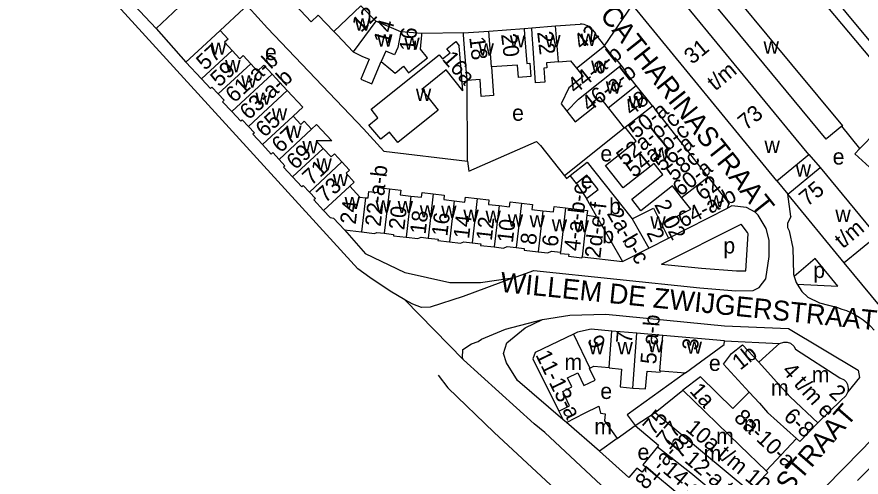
# Model space of a CAD drawing. Extents: x 160673 to 161924, y 382258 to 384145.
# Drawn here: x 160762.5 to 160974.8, y 382888.8 to 383004.5 of the extents above; entities that cross this region are included whole.
import ezdxf

# ---------------------------------------------------------------- set-up
doc = ezdxf.new("R2010")
doc.units = 0
for name, color, linetype in [('BLT_Basislijn', 7, 'Continuous'), ('BLT_Bebouwing', 7, 'Continuous'), ('BLT_Centroide', 7, 'Continuous'), ('BLT_Huisnummer', 7, 'Continuous'), ('BLT_Huisnummer_ tussenligend', 7, 'Continuous'), ('BLT_Huisnummer_reeks', 7, 'Continuous'), ('BLT_Onderdoorgang_en_onderverdeling', 7, 'Continuous'), ('BLT_Onderverdeling_panden', 7, 'Continuous'), ('BLT_Straatnaam', 7, 'Continuous'), ('BLT_Vlakafsluiter', 7, 'Continuous')]:
    doc.layers.add(name, color=color, linetype=linetype)

msp = doc.modelspace()

# ---------------------------------------------------------------- linework, layer by layer
at = {"layer": 'BLT_Basislijn'}
for p, q in [((160797.51, 383001.64), (160805.02, 382993.11)), ((160874.79, 383000.47), (160864.31, 383000.33)), ((160890.02, 383001.64), (160891.98, 383001.79)), ((160875.8, 382968.26), (160875.69, 382988.54)), ((160974.46, 382971.4), (160969.96, 382977.04)), ((160915.17, 382976.53), (160900.18, 382964.55)), ((160903.21, 382962.64), (160905.71, 382958.85)), ((160957.08, 382954.31), (160956.31, 382959.97)), ((160844.89, 382950.95), (160850.14, 382944.96)), ((160958.71, 382937.3), (160968.88, 382936.83)), ((160940.45, 382923.03), (160954.21, 382922.38)), ((160974.01, 382915.66), (160974.4, 382913.88)), ((160930.62, 382915.04), (160915.98, 382904.45)), ((160898.77, 382905.41), (160899.8, 382903.34)), ((160900.73, 382902.52), (160899.79, 382903.27)), ((160913.4, 382898.5), (160917.97, 382901.75)), ((160916.4, 382888.68), (160909.03, 382895.35))]:
    msp.add_line(p, q, dxfattribs=at)
for points in [[(160860.05, 382933.37), (160856.38, 382935.54), (160851.3, 382939), (160848.28, 382941.16), (160762.53, 383035.18)], [(160951.81, 383024.3), (160982.58, 382987.62), (160979.94, 382985.6), (160984.16, 382980.62)], [(160963.06, 383015.22), (160978.82, 382996.13), (160992.96, 383008.58), (160973.33, 383023.89)], [(160813.63, 383001.08), (160819.55, 383006.65), (160820.69, 383007.01), (160825.54, 383001.66), (160849.63, 382976.37), (160854.76, 382970.79), (160875.8, 382968.26)], [(160875.8, 382968.26), (160876.19, 382965.75), (160893.19, 382973.16), (160894.15, 382972.21), (160900.18, 382964.55)], [(160900.18, 382964.55), (160900.73, 382963.86), (160901.65, 382964.6)], [(160887.14, 382938.82), (160892.45, 382940.72), (160934.23, 382936.35), (160943.29, 382935.67), (160947.63, 382935.71), (160949.16, 382936.51), (160950.81, 382938.68), (160951.69, 382944.29), (160951.69, 382948.35), (160950.91, 382951.27), (160948.9, 382954.68), (160948.17, 382955.38), (160945.97, 382956.59), (160942.3, 382956.99), (160941.17, 382956.43)], [(160957.08, 382954.31), (160956.3, 382952.54), (160956.27, 382951.57), (160956.66, 382950.72), (160957.58, 382946.36), (160957.74, 382939.86), (160957.94, 382939.27)], [(160924.61, 382942.38), (160944.6, 382952.39)], [(160945.82, 382940.69), (160946.35, 382949.93), (160946.2, 382950.27), (160944.6, 382952.39)], [(160887.14, 382938.82), (160879.05, 382937.63), (160871.34, 382937.67), (160860.15, 382940.12), (160850.14, 382944.96)], [(160968.88, 382936.83), (160963.2, 382943.73), (160957.94, 382939.27)], [(160924.61, 382942.38), (160934.67, 382941.33), (160943.45, 382940.67), (160945.82, 382940.69)], [(160887.14, 382938.82), (160874.73, 382934.18), (160866.44, 382931.51), (160864.29, 382931.44), (160862.06, 382932.26), (160860.05, 382933.37)], [(160957.94, 382939.27), (160958.43, 382937.77), (160958.71, 382937.3)], [(160958.71, 382937.3), (160959.85, 382935.43), (160961.39, 382934.02), (160964.3, 382932.61), (160968.85, 382931.43), (160969.96, 382931.06)], [(160969.96, 382931.06), (160971.09, 382930.66), (160972.19, 382930.19), (160973.25, 382929.64), (160974.28, 382929.02), (160975.27, 382928.34), (160976.2, 382927.59), (160977.09, 382926.78), (160978.08, 382925.73)], [(160878.49, 382922.86), (160879.36, 382923.44), (160885.38, 382925.99), (160894.65, 382928.42)], [(160899.79, 382903.27), (160888.35, 382913.06), (160885.58, 382917.54), (160884.9, 382919.9), (160885.69, 382922.52), (160890.29, 382926.32), (160894.65, 382928.42)], [(160894.65, 382928.42), (160901.58, 382929.48), (160910.63, 382929.79), (160940.41, 382926.83), (160956.55, 382926.15), (160974.01, 382915.66)], [(160874.8, 382918.27), (160874.53, 382918.82), (160874.68, 382920.86), (160876.8, 382922.32), (160878.49, 382922.86)], [(160929.92, 382867.53), (160895.25, 382900), (160892.57, 382902.21), (160874.8, 382918.27)], [(160868.45, 382914.46), (160870.91, 382911.22), (160882.54, 382900), (160909.7, 382874.79), (160911.87, 382872.51), (160924.34, 382861.03)], [(160974.4, 382913.88), (160971.41, 382910.23)], [(160986.23, 382906.1), (160979.59, 382900.39), (160974.77, 382895.48), (160965.77, 382886.24), (160962.43, 382882.73), (160958.51, 382877.83), (160957.53, 382876.57)]]:
    msp.add_lwpolyline(points, dxfattribs=at)
at = {"layer": 'BLT_Bebouwing'}
for p, q in [((160790.69, 383008.95), (160797.51, 383001.64)), ((160803.22, 383006.98), (160797.51, 383001.64)), ((160852.76, 383003.41), (160849.04, 383007.31)), ((160838.29, 383004.96), (160842.23, 383000.83)), ((160859.08, 383000.74), (160852.76, 383003.41)), ((160897.97, 383002.25), (160904.18, 383002.73)), ((160864.31, 383000.33), (160859.08, 383000.74)), ((160874.79, 383000.47), (160881.14, 383000.96)), ((160881.14, 383000.96), (160890.02, 383001.64)), ((160891.98, 383001.79), (160897.97, 383002.25)), ((160874.68, 382985.92), (160873.68, 382997.28)), ((160826.7, 382990.14), (160830.51, 382986.03)), ((160922.29, 382982.15), (160918.2, 382987.26)), ((160922.29, 382982.15), (160922.87, 382981.37)), ((160927.24, 382975.83), (160922.87, 382981.37)), ((160915.17, 382976.53), (160915.48, 382976.79)), ((160931.7, 382970.18), (160927.24, 382975.83)), ((160936.3, 382964.33), (160931.7, 382970.18)), ((160961.64, 382969.95), (160964.45, 382966.67)), ((160903.21, 382962.64), (160901.65, 382964.6)), ((160953.59, 382963.33), (160956.31, 382959.97)), ((160908.24, 382954.44), (160905.71, 382958.85)), ((160844.89, 382950.95), (160849.17, 382950.45)), ((160914.77, 382943), (160921.44, 382946.39)), ((160902.46, 382924.75), (160892.82, 382920.11)), ((160918.37, 382924.95), (160912.13, 382925.5)), ((160924.88, 382924.39), (160918.37, 382924.95)), ((160940.45, 382923.03), (160924.88, 382924.39)), ((160924.32, 382915.54), (160930.62, 382915.04)), ((160922.98, 382905.02), (160929.95, 382910.64)), ((160915.98, 382904.45), (160917.97, 382901.75)), ((160909.03, 382895.35), (160900.73, 382902.52)), ((160913.4, 382898.5), (160909.03, 382895.35)), ((160950.91, 382890.34), (160958.56, 382898.5)), ((160982.84, 382896.92), (160973.86, 382887.97))]:
    msp.add_line(p, q, dxfattribs=at)
for points in [[(160969.96, 382977.04), (160966.19, 382973.94), (160965.95, 382973.74), (160944.25, 383000), (160933.11, 383013.54), (160933.33, 383013.72), (160937.19, 383016.89)], [(160937.19, 383016.89), (160951.09, 383000), (160970.05, 382977.11), (160969.96, 382977.04)], [(160961.64, 382969.95), (160958.42, 382973.78), (160925.38, 383014.05)], [(160832.49, 383007.52), (160836.53, 383003.28), (160838.29, 383004.96)], [(160953.59, 382963.33), (160917.33, 383007.56)], [(160906.37, 383001.95), (160905.99, 383002.25), (160905.57, 383002.48), (160905.12, 383002.64), (160904.64, 383002.72), (160904.18, 383002.73)], [(160813.63, 383001.08), (160812.5, 383000.03), (160809.11, 382996.9), (160805.02, 382993.11)], [(160813.63, 383001.08), (160814.66, 383000), (160815.62, 382998.95), (160814.74, 382998.13), (160816.65, 382996.06)], [(160842.23, 383000.83), (160843.02, 383000), (160847.11, 382995.72)], [(160856.51, 382991.3), (160857.6, 382990.39), (160859.73, 382992.09), (160861.02, 382990.47), (160861.84, 382991.13), (160865.74, 382994.25), (160864.02, 382996.41), (160864.3, 383000), (160864.31, 383000.33)], [(160875.69, 382988.54), (160875.15, 382995.49), (160874.82, 383000), (160874.79, 383000.47)], [(160890.02, 383001.64), (160890.15, 383000), (160890.72, 382992.8), (160891.5, 382992.86), (160891.75, 382989.54), (160888.6, 382989.3), (160888.36, 382992.42), (160881.83, 382991.92)], [(160898.7, 382993.24), (160895.66, 382993), (160895.76, 382991.68), (160894.97, 382991.62), (160895.24, 382988.08), (160892.94, 382987.9), (160892.29, 382996.64), (160892.04, 383000), (160891.98, 383001.79)], [(160906.37, 383001.95), (160906.88, 383001.34), (160907.23, 383001.3), (160908.01, 383000.31), (160907.89, 383000.21), (160908.06, 383000), (160910.25, 382997.24)], [(160851.58, 382981.28), (160868.69, 382994.96), (160869.5, 382993.95), (160871.43, 382995.49), (160870.62, 382996.5), (160872.87, 382998.3), (160873.68, 382997.28)], [(160914.43, 382992.34), (160912.98, 382994.18), (160912.71, 382994.14), (160910.25, 382997.24)], [(160816.65, 382996.06), (160818.57, 382993.99), (160819.41, 382994.77), (160821.31, 382992.72)], [(160847.11, 382995.72), (160849.26, 382994.66), (160851.1, 382993.88), (160848.97, 382988.84), (160851.77, 382987.66), (160854.14, 382993.27)], [(160805.02, 382993.11), (160808.96, 382988.94)], [(160821.31, 382992.72), (160823.03, 382990.86), (160824.65, 382992.36), (160826.7, 382990.14)], [(160854.14, 382993.27), (160856.51, 382991.3)], [(160881.83, 382991.92), (160882.38, 382984.77), (160879.29, 382984.53), (160878.96, 382988.8), (160875.69, 382988.54)], [(160898.7, 382993.24), (160901.74, 382993.49), (160903.21, 382991.64)], [(160918.2, 382987.26), (160915.71, 382990.42), (160915.79, 382990.62), (160914.43, 382992.34)], [(160874.68, 382985.92), (160870.46, 382991.17), (160864.32, 382986.24), (160868.47, 382981.06), (160858.3, 382972.9), (160856.2, 382975.52), (160854.06, 382973.81), (160851.01, 382977.28), (160853.31, 382979.13), (160851.58, 382981.28)], [(160903.21, 382991.64), (160904.9, 382989.51), (160901.29, 382986.66), (160899.34, 382982.68), (160900.81, 382980.82)], [(160808.96, 382988.94), (160811.22, 382986.49), (160811.58, 382986.83), (160813.13, 382985.15)], [(160830.51, 382986.03), (160834.43, 382981.81), (160831.98, 382979.56)], [(160813.13, 382985.15), (160814.62, 382983.54), (160814.26, 382983.2), (160816.55, 382980.72)], [(160900.81, 382980.82), (160902.92, 382978.14), (160907.77, 382981.96), (160907.06, 382982.87), (160908.98, 382984.39), (160911.14, 382981.65)], [(160911.14, 382981.65), (160913.74, 382978.35), (160915.17, 382976.53)], [(160816.55, 382980.72), (160818.83, 382978.26), (160819.2, 382978.6), (160820.76, 382976.92)], [(160831.98, 382979.56), (160833.9, 382977.49), (160834.78, 382978.3), (160836.61, 382976.32)], [(160836.61, 382976.32), (160837.88, 382977.49), (160841.69, 382973.38), (160837.77, 382973.33), (160839.55, 382971.4)], [(160820.76, 382976.92), (160822.23, 382975.33), (160821.88, 382975.01), (160824.26, 382972.42)], [(160910.49, 382967.15), (160918.25, 382973.27), (160915.48, 382976.79)], [(160978.58, 382975.62), (160974.46, 382971.4)], [(160824.26, 382972.42), (160826.47, 382970.04), (160826.85, 382970.39), (160828.49, 382968.62)], [(160839.55, 382971.4), (160841.5, 382969.3), (160842.36, 382970.1), (160844.25, 382968.05)], [(160974.46, 382971.4), (160973.2, 382970.11), (160976.88, 382966.73), (160978.52, 382965.21), (160977.89, 382964.49)], [(160828.49, 382968.62), (160829.92, 382967.06), (160829.57, 382966.74), (160831.85, 382964.27)], [(160844.25, 382968.05), (160846.15, 382966), (160845.28, 382965.2), (160847.33, 382962.98), (160846.2, 382961.93)], [(160901.65, 382964.6), (160905.88, 382968), (160916.91, 382954.2), (160917.2, 382953.7)], [(160924.96, 382964.86), (160922.74, 382967.67), (160914.94, 382961.52), (160910.49, 382967.15)], [(160964.45, 382966.67), (160978.68, 382949.37)], [(160831.85, 382964.27), (160834.14, 382961.8), (160834.52, 382962.15), (160836.07, 382960.48)], [(160905.71, 382958.85), (160908.68, 382961.1), (160905.81, 382964.71), (160903.21, 382962.64)], [(160929.63, 382959.07), (160927.33, 382962), (160919.39, 382955.75), (160917.1, 382958.67), (160924.96, 382964.86)], [(160941.17, 382956.43), (160941.57, 382957.65), (160936.3, 382964.33)], [(160836.07, 382960.48), (160837.6, 382958.82), (160837.22, 382958.48), (160839.63, 382955.86)], [(160846.2, 382961.93), (160848.71, 382959.22), (160850.15, 382959.06)], [(160850.83, 382958.98), (160851.01, 382960.6), (160853.21, 382960.34), (160853.36, 382961.58), (160856.19, 382961.25)], [(160856.19, 382961.25), (160859.03, 382960.93), (160858.9, 382959.8), (160861.6, 382959.48)], [(160861.6, 382959.48), (160864.29, 382959.17), (160864.43, 382960.36), (160867.2, 382960.04)], [(160867.2, 382960.04), (160869.97, 382959.72), (160869.84, 382958.58), (160872.5, 382958.27)], [(160850.15, 382959.06), (160850.83, 382958.98)], [(160872.5, 382958.27), (160875.15, 382957.97), (160875.29, 382959.17), (160878.24, 382958.83)], [(160878.24, 382958.83), (160881.2, 382958.49), (160881.07, 382957.37), (160883.74, 382957.06)], [(160883.74, 382957.06), (160886.4, 382956.76), (160886.55, 382957.99), (160889.35, 382957.67)], [(160924.57, 382952.4), (160931.94, 382956.15), (160929.63, 382959.07)], [(160970.55, 382942.67), (160956.31, 382959.97)], [(160839.63, 382955.86), (160841.26, 382954.09), (160842.1, 382953.87), (160844.89, 382950.95)], [(160889.35, 382957.67), (160892.16, 382957.35), (160892.02, 382956.1), (160894.74, 382955.79)], [(160894.74, 382955.79), (160897.47, 382955.47), (160897.62, 382956.81), (160900.44, 382956.48)], [(160900.44, 382956.48), (160903.26, 382956.16), (160905.96, 382955.85), (160905.83, 382954.62)], [(160917.2, 382953.7), (160922.54, 382956.41), (160924.57, 382952.4)], [(160926.37, 382948.86), (160941.17, 382956.43)], [(160905.83, 382954.62), (160908.1, 382954.36)], [(160908.1, 382954.36), (160908.24, 382954.44)], [(160849.17, 382950.45), (160852.45, 382950.08), (160853, 382950.32), (160854.9, 382950.1)], [(160854.9, 382950.1), (160857.24, 382949.83), (160857.19, 382949.47), (160860.4, 382949.1)], [(160860.4, 382949.1), (160863.33, 382948.76), (160864.14, 382949.11), (160865.92, 382948.91)], [(160865.92, 382948.91), (160868.4, 382948.62), (160868.36, 382948.26), (160871.3, 382947.92)], [(160871.3, 382947.92), (160874.06, 382947.6), (160874.92, 382947.97), (160876.96, 382947.74)], [(160876.96, 382947.74), (160879.15, 382947.48), (160879.11, 382947.05), (160882.54, 382946.66)], [(160921.44, 382946.39), (160926.37, 382948.86)], [(160882.54, 382946.66), (160884.84, 382946.39), (160885.79, 382946.8), (160888.07, 382946.54)], [(160888.07, 382946.54), (160890.07, 382946.31), (160890.02, 382945.87), (160893.55, 382945.46)], [(160893.55, 382945.46), (160895.99, 382945.18), (160896.96, 382945.6), (160899.16, 382945.35)], [(160899.16, 382945.35), (160899.12, 382945.06), (160901.3, 382944.82), (160901.24, 382944.32), (160904.59, 382943.94), (160904.62, 382944.17)], [(160904.62, 382944.17), (160914.77, 382943)], [(160999.49, 382938.63), (160984.22, 382926.07), (160970.55, 382942.67)], [(160912.13, 382925.5), (160906.93, 382925.99), (160903.49, 382925.26), (160902.46, 382924.75)], [(160930.62, 382915.04), (160940.38, 382922.14), (160940.45, 382923.03)], [(160946.59, 382910.15), (160940.15, 382917.16), (160942.16, 382919.87), (160944.91, 382922.09), (160949.02, 382917.69)], [(160949.02, 382917.69), (160953.51, 382921.76), (160954.21, 382922.38)], [(160954.21, 382922.38), (160955.33, 382922.72), (160956.18, 382922.72), (160957.04, 382922.47), (160957.89, 382921.7), (160958.28, 382920.96), (160969.41, 382913.72), (160970.47, 382913.22), (160970.98, 382912.71), (160971.32, 382912.11), (160971.49, 382911.09), (160971.41, 382910.23)], [(160892.82, 382920.11), (160892.27, 382918.55), (160898.77, 382905.41)], [(160903.53, 382915.01), (160905.1, 382911.79), (160907.91, 382913.15), (160906.46, 382916.14), (160906.61, 382916.22)], [(160906.61, 382916.22), (160907.54, 382916.67), (160911.41, 382916.36)], [(160911.41, 382916.36), (160911.4, 382916.26), (160914.52, 382915.93), (160914.17, 382911.46), (160917.39, 382911.2)], [(160917.39, 382911.2), (160920.6, 382910.95), (160920.96, 382915.42), (160924.29, 382915.16), (160924.32, 382915.54)], [(160900.9, 382910.9), (160902.06, 382911.46), (160900.94, 382913.76), (160903.53, 382915.01)], [(160946.59, 382910.15), (160942.54, 382906.07), (160934.4, 382914.01), (160929.95, 382910.64)], [(160898.77, 382905.41), (160901.49, 382906.73), (160899.74, 382910.34), (160900.9, 382910.9)], [(160971.41, 382910.23), (160970.9, 382909.2), (160969.69, 382908.09), (160963.92, 382902.48)], [(160900.73, 382902.52), (160905.26, 382904.91), (160908.8, 382906.64), (160909.27, 382904.89), (160910.41, 382904.74), (160910.25, 382902.96), (160913.4, 382898.5)], [(160917.97, 382901.75), (160922.98, 382905.02)], [(160917.97, 382901.75), (160923.86, 382896.83), (160923.54, 382896.42)], [(160958.56, 382898.5), (160959.33, 382897.76), (160963.92, 382902.48)], [(160923.54, 382896.42), (160919.93, 382891.86), (160920.61, 382891.34)], [(160920.61, 382891.34), (160919.71, 382890.07), (160918.38, 382891.08), (160916.4, 382888.68)], [(160946.79, 382885.26), (160951.36, 382889.94), (160950.91, 382890.34)]]:
    msp.add_lwpolyline(points, dxfattribs=at)
at = {"layer": 'BLT_Onderdoorgang_en_onderverdeling'}
for p, q in [((160953.59, 382963.33), (160961.64, 382969.95)), ((160956.31, 382959.97), (160964.45, 382966.67))]:
    msp.add_line(p, q, dxfattribs=at)
at = {"layer": 'BLT_Onderverdeling_panden'}
for p, q in [((160842.23, 383000.83), (160849.04, 383007.31)), ((160852.76, 383003.41), (160847.11, 382995.72)), ((160881.83, 382991.92), (160881.14, 383000.96)), ((160898.7, 382993.24), (160897.97, 383002.25)), ((160903.21, 382991.64), (160910.25, 382997.24)), ((160816.65, 382996.06), (160808.96, 382988.94)), ((160821.31, 382992.72), (160813.13, 382985.15)), ((160826.7, 382990.14), (160816.55, 382980.72)), ((160830.51, 382986.03), (160820.76, 382976.92)), ((160911.14, 382981.65), (160918.2, 382987.26)), ((160915.48, 382976.79), (160922.29, 382982.15)), ((160831.98, 382979.56), (160824.26, 382972.42)), ((160836.61, 382976.32), (160828.49, 382968.62)), ((160839.55, 382971.4), (160831.85, 382964.27)), ((160844.25, 382968.05), (160836.07, 382960.48)), ((160929.63, 382959.07), (160936.3, 382964.33)), ((160846.2, 382961.93), (160839.63, 382955.86)), ((160856.19, 382961.25), (160854.9, 382950.1)), ((160867.2, 382960.04), (160865.92, 382948.91)), ((160850.15, 382959.06), (160849.17, 382950.45)), ((160861.6, 382959.48), (160860.4, 382949.1)), ((160872.5, 382958.27), (160871.3, 382947.92)), ((160878.24, 382958.83), (160876.96, 382947.74)), ((160883.74, 382957.06), (160882.54, 382946.66)), ((160889.35, 382957.67), (160888.07, 382946.54)), ((160894.74, 382955.79), (160893.55, 382945.46)), ((160900.44, 382956.48), (160899.16, 382945.35)), ((160905.83, 382954.62), (160904.62, 382944.17)), ((160908.24, 382954.44), (160914.77, 382943)), ((160917.2, 382953.7), (160921.44, 382946.39)), ((160924.57, 382952.4), (160926.37, 382948.86)), ((160978.68, 382949.37), (160970.55, 382942.67)), ((160902.46, 382924.75), (160906.61, 382916.22)), ((160911.41, 382916.36), (160912.13, 382925.5)), ((160917.39, 382911.2), (160918.37, 382924.95)), ((160949.02, 382917.69), (160954.24, 382911.92)), ((160944.27, 382896.76), (160929.95, 382910.64)), ((160946.59, 382910.15), (160949.23, 382907.39)), ((160949.23, 382907.39), (160951.25, 382905.07)), ((160922.98, 382905.02), (160946.79, 382885.26)), ((160951.25, 382905.07), (160958.56, 382898.5)), ((160950.91, 382890.34), (160944.27, 382896.76))]:
    msp.add_line(p, q, dxfattribs=at)
for points in [[(160859.08, 383000.74), (160858.3, 382996.85), (160857.5, 382994.95), (160855.25, 382995.89), (160854.14, 382993.27)], [(160900.81, 382980.82), (160903.76, 382983.86), (160914.43, 382992.34)], [(160924.32, 382915.54), (160924.18, 382915.55), (160924.88, 382924.39)], [(160954.24, 382911.92), (160956.94, 382909.02), (160963.92, 382902.48)], [(160923.54, 382896.42), (160931.94, 382889.85), (160943.02, 382880.61)], [(160920.61, 382891.34), (160939.25, 382875.98)]]:
    msp.add_lwpolyline(points, dxfattribs=at)
at = {"layer": 'BLT_Vlakafsluiter'}
for p, q in [((160910.25, 382997.24), (160917.33, 383007.56)), ((160860.05, 382933.37), (160874.8, 382918.27))]:
    msp.add_line(p, q, dxfattribs=at)

# ---------------------------------------------------------------- texts
at = {"layer": 'BLT_Centroide'}
for s, p in [('w', (160847.5, 383001.05)), ('w', (160853.09, 382997.05)), ('w', (160859.94, 382996.25)), ('w', (160886.44, 382996.83)), ('w', (160895.34, 382996.86)), ('w', (160904.27, 382997.19)), ('w', (160950.24, 382995.27)), ('w', (160811.3, 382995)), ('e', (160824.9, 382993.66)), ('w', (160878.58, 382994.77)), ('w', (160814.89, 382990.59)), ('w', (160906.89, 382990.45)), ('w', (160818.93, 382986.72)), ('w', (160910.57, 382985.25)), ('w', (160822.52, 382982.41)), ('w', (160862.84, 382983.41)), ('w', (160916.31, 382981.59)), ('w', (160826.62, 382978.47)), ('e', (160887.03, 382978.4)), ('w', (160830.23, 382974.09)), ('w', (160834.31, 382970.22)), ('w', (160950.48, 382970.29)), ('e', (160909.22, 382968.17)), ('w', (160922.62, 382968.56)), ('w', (160837.84, 382965.91)), ('e', (160967.62, 382967.39)), ('w', (160958.32, 382964.37)), ('w', (160841.94, 382961.97)), ('e', (160904.29, 382961.36)), ('w', (160844.91, 382956.19)), ('w', (160852.69, 382955.3)), ('w', (160858.25, 382955.17)), ('b', (160911.41, 382954.92)), ('w', (160936.41, 382956.59)), ('w', (160863.8, 382954.09)), ('w', (160869.2, 382953.98)), ('w', (160874.78, 382952.95)), ('w', (160880.34, 382952.75)), ('w', (160968.29, 382952.96)), ('w', (160885.94, 382951.8)), ('w', (160891.41, 382951.58)), ('w', (160897, 382950.56)), ('w', (160921.78, 382951.3)), ('w', (160902.48, 382950.33)), ('b', (160909.7, 382947.62)), ('p', (160940.13, 382945.03)), ('p', (160962.73, 382938.86)), ('w', (160906.3, 382919.69)), ('w', (160913.52, 382919.69)), ('w', (160921.2, 382920.14)), ('w', (160930.91, 382919.81)), ('m', (160900.18, 382915.75)), ('e', (160936.5, 382915.49)), ('m', (160962.35, 382912.59)), ('e', (160909.2, 382908.44)), ('m', (160952.08, 382909.31)), ('m', (160945.25, 382900.3)), ('m', (160907.7, 382899.54)), ('m', (160938.32, 382897.12)), ('e', (160918.55, 382893.13)), ('m', (160935.18, 382892.78))]:
    msp.add_text(s, height=4, dxfattribs=at).set_placement(p)
at = {"layer": 'BLT_Huisnummer'}
for s, rotation, p in [('14', 74.7223, (160855.95, 382997.47)), ('16', 85.4305, (160862.7, 382995.81)), ('22', 276.6152, (160893.31, 383000.73)), ('42', 38.4409, (160904.48, 382996.05)), ('18', 276.8808, (160876.24, 382999.37)), ('57', 42.7705, (160809.86, 382990.9)), ('16a', 311.0189, (160869.26, 382993.82)), ('65', 42.7571, (160824.79, 382974.04)), ('69', 42.7541, (160832.57, 382965.91)), ('73', 42.7541, (160840.09, 382957.56)), ('24', 83.4143, (160847.71, 382952.23)), ('20', 83.417, (160859.91, 382950.81)), ('16', 83.4164, (160870.73, 382949.21)), ('12', 83.4206, (160881.91, 382948.11)), ('8', 83.424, (160893.01, 382947.06)), ('2', 296.9508, (160920.7, 382950.21)), ('9', 294.0342, (160905.83, 382923.39)), ('3', 85.4877, (160933.75, 382920.63))]:
    msp.add_text(s, height=4, rotation=rotation, dxfattribs=at).set_placement(p)
at = {"layer": 'BLT_Huisnummer_ tussenligend'}
for s, rotation, p in [('12', 43.6421, (160849.04, 383000.47)), ('20', 276.8808, (160884.24, 383000.15)), ('59', 42.7705, (160813.42, 382986.71)), ('48', 38.2432, (160917.06, 382979.49)), ('67', 42.7571, (160828.83, 382970.13)), ('71', 42.7541, (160836.55, 382961.96)), ('18', 83.4164, (160865.27, 382949.72)), ('14', 83.4206, (160876.2, 382948.59)), ('10', 83.424, (160887.21, 382947.54)), ('6', 83.4132, (160898.46, 382946.58)), ('7', 85.4933, (160917.12, 382922.3))]:
    msp.add_text(s, height=4, rotation=rotation, dxfattribs=at).set_placement(p)
at = {"layer": 'BLT_Huisnummer_reeks'}
for s, rotation, p in [('31', 39.4584, (160932.3, 382992.42)), ('44-a-b', 38.4409, (160902.92, 382985.01)), ('61-a-b', 42.7621, (160817.21, 382982.73)), ('46-a-b', 38.2432, (160906.44, 382980.5)), ('t/m', 39.4584, (160938.1, 382985.76)), ('63-a-b', 42.7571, (160820.82, 382978.43)), ('50-a', 38.2394, (160918.28, 382973.74)), ('73', 39.4584, (160945.83, 382975.84)), ('52a-b-c', 38.2499, (160915.23, 382966.91)), ('54a-b-c', 38.2499, (160917.65, 382963.95)), ('56-a', 38.2499, (160924.7, 382965.45)), ('58c', 38.2489, (160927.71, 382963.02)), ('22-a-b', 83.417, (160853.97, 382951.68)), ('60-a', 38.2531, (160929.35, 382959.22)), ('62', 38.2531, (160935.02, 382958.17)), ('4-a-b-c', 83.4132, (160904, 382945.49)), ('75', 39.4547, (160961.24, 382956.71)), ('64-a-b', 26.9368, (160929.99, 382951.42)), ('2d-e-f', 83.4156, (160909.21, 382943.73)), ('2 02', 296.9508, (160922.69, 382957.33)), ('2a-b-c', 300.1158, (160910.74, 382955.1)), ('t/m', 39.4577, (160970.15, 382946.09)), ('5-a-b', 85.4903, (160923.24, 382917.08)), ('11-13-a', 295.9125, (160892.83, 382919.56)), ('1b', 38.7938, (160944.36, 382915.52)), ('4 t/m e', 312.1486, (160954.69, 382915.38)), ('1a', 311.6351, (160931.46, 382910.33)), ('2', 317.0348, (160966.44, 382909.61)), ('75', 49.244, (160922.55, 382899.09)), ('8a-10-a', 316.8457, (160942.55, 382903.4)), ('6-8', 316.612, (160955.05, 382903.7)), ('77', 49.244, (160925.95, 382896.15)), ('10a t/m 10d', 320.3835, (160930.42, 382900.61)), ('81-a-b', 49.244, (160920.63, 382885.42)), ('79', 49.244, (160929.36, 382893.22)), ('12-a t/m c', 320.1709, (160930.13, 382892.73)), ('14-a t/m e', 320.1692, (160924.69, 382890.12))]:
    msp.add_text(s, height=4, rotation=rotation, dxfattribs=at).set_placement(p)
at = {"layer": 'BLT_Straatnaam'}
for s, height, rotation, p in [('ST CATHARINASTRAAT', 5, 308.492, (160902.43, 383013.03)), ('WILLEM DE ZWIJGERSTRAAT', 4.9999, 354.1522, (160883.87, 382935.4)), ('HOOGSTRAAT', 5, 49.0877, (160943.23, 382869.02))]:
    msp.add_text(s, height=height, rotation=rotation, dxfattribs=at).set_placement(p)

doc.saveas('drawing.dxf')
